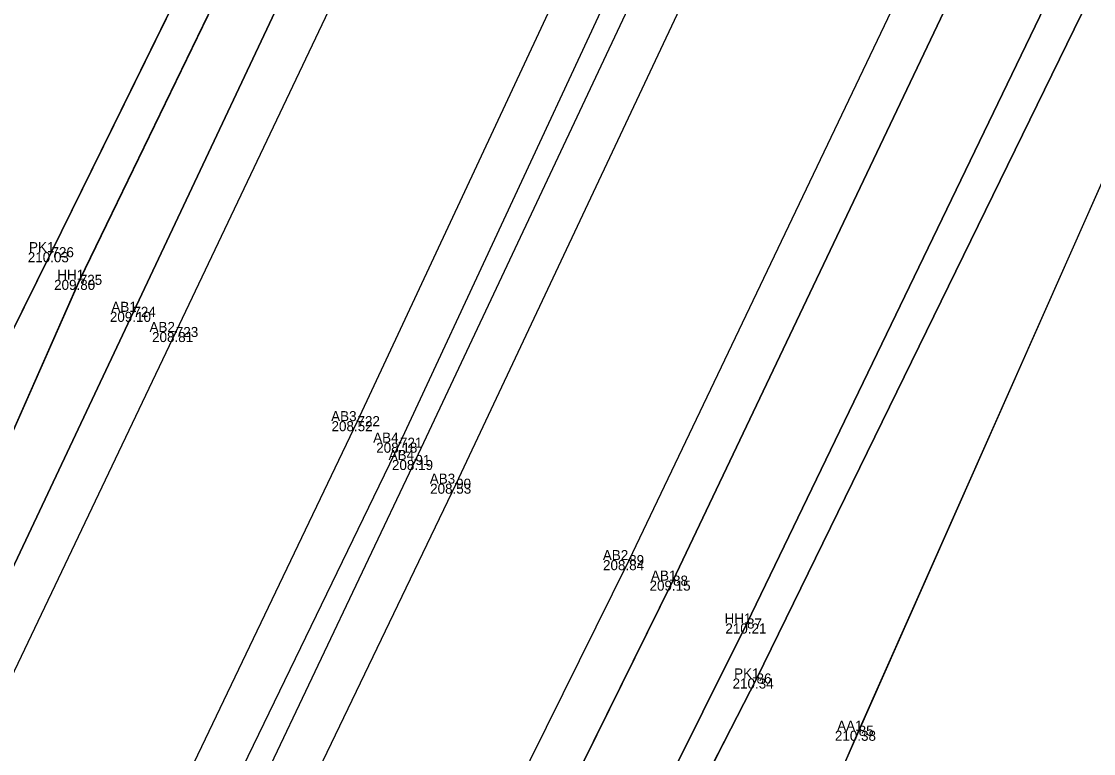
# Model space of a CAD drawing. Extents: x -263091 to -262565, y -1238731 to -1237092.
# Drawn here: x -262786.65 to -262765.31, y -1237663.76 to -1237649.19 of the extents above; entities that cross this region are included whole.
import ezdxf

# ---------------------------------------------------------------- set-up
doc = ezdxf.new("R2010")
doc.units = 0
for name, color, linetype in [('01_Hrana_betónu', 7, 'Continuous'), ('02_Oplotenie', 7, 'Continuous'), ('03_Asfalt', 7, 'Continuous'), ('05_Hrana_terénu', 7, 'Continuous'), ('Groma (21)', 7, 'Continuous'), ('Groma (22)', 7, 'Continuous'), ('Groma (23)', 7, 'Continuous'), ('Groma (24)', 7, 'Continuous'), ('U005_Betónové_panely', 7, 'Continuous'), ('U005_Zeleň_mimo', 7, 'Continuous'), ('U005_Zeleň_vnútro', 7, 'Continuous'), ('U005_Zeleň_zatrávňovač', 7, 'Continuous')]:
    doc.layers.add(name, color=color, linetype=linetype)

msp = doc.modelspace()

# ---------------------------------------------------------------- linework, layer by layer
at = {"layer": '01_Hrana_betónu'}
for points in [[(-262786.432, -1237675.911), (-262784.052, -1237670.991), (-262777.997, -1237658.39), (-262770.22, -1237641.884), (-262760.517, -1237621.621), (-262751.199, -1237602.266), (-262746.917, -1237592.345), (-262743.67, -1237583.59), (-262741.234, -1237574.416), (-262739.924, -1237566.213), (-262738.929, -1237556.596), (-262738.741, -1237547.665), (-262738.506, -1237524.618), (-262738.316, -1237501.393), (-262738.103, -1237478.98), (-262737.841, -1237459.175), (-262737.82, -1237425.07), (-262737.772, -1237401.714), (-262737.893, -1237377.738), (-262738.012, -1237356.488), (-262737.973, -1237332.295), (-262738.006, -1237318.022), (-262737.947, -1237310.645)], [(-262738.855, -1237311.192), (-262738.946, -1237318.051), (-262738.849, -1237332.413), (-262738.867, -1237356.312), (-262738.748, -1237377.69), (-262738.758, -1237401.69), (-262738.753, -1237425.185), (-262738.668, -1237459.096), (-262739.01, -1237478.875), (-262739.257, -1237501.361), (-262739.436, -1237524.506), (-262739.635, -1237547.624), (-262739.863, -1237556.5), (-262740.784, -1237566.075), (-262742.123, -1237574.161), (-262744.555, -1237583.315), (-262747.793, -1237592.067), (-262752.033, -1237601.877), (-262761.381, -1237621.164), (-262771.059, -1237641.465), (-262778.806, -1237657.918), (-262784.861, -1237670.667), (-262787.201, -1237675.529)], [(-262739.343, -1237311.485), (-262739.423, -1237318.909), (-262739.337, -1237332.42), (-262739.334, -1237355.849), (-262739.135, -1237377.701), (-262739.178, -1237401.786), (-262739.257, -1237424.031), (-262739.458, -1237458.924), (-262739.421, -1237479.296), (-262739.718, -1237500.116), (-262739.917, -1237524.824), (-262740.163, -1237546.913), (-262740.342, -1237556.649), (-262741.144, -1237564.78), (-262742.646, -1237573.838), (-262744.715, -1237582.455), (-262748.007, -1237591.229), (-262752.529, -1237601.669), (-262761.584, -1237620.386), (-262771.44, -1237641.076), (-262779.114, -1237657.574), (-262785.318, -1237670.364), (-262787.643, -1237675.31)], [(-262788.441, -1237674.914), (-262786.102, -1237669.974), (-262779.96, -1237657.146), (-262772.255, -1237640.671), (-262762.405, -1237620.082), (-262753.353, -1237601.237), (-262748.855, -1237590.92), (-262745.54, -1237582.117), (-262743.431, -1237573.688), (-262742.016, -1237564.7), (-262741.168, -1237556.501), (-262740.979, -1237546.892), (-262740.851, -1237524.752), (-262740.671, -1237500.08), (-262740.394, -1237479.483), (-262740.216, -1237458.955), (-262740.117, -1237423.647), (-262740.094, -1237401.75), (-262740.13, -1237377.708), (-262740.243, -1237355.929), (-262740.317, -1237332.345), (-262740.44, -1237318.894), (-262740.323, -1237312.076)], [(-262744.671, -1237314.693), (-262744.322, -1237332.28), (-262744.032, -1237356.103), (-262743.621, -1237377.876), (-262743.427, -1237401.834), (-262743.334, -1237423.507), (-262743.665, -1237455.163), (-262743.89, -1237458.66), (-262743.816, -1237479.543), (-262744.125, -1237500.374), (-262744.256, -1237524.891), (-262744.407, -1237545.149), (-262744.747, -1237556.085), (-262745.544, -1237564.593), (-262746.648, -1237572.023), (-262748.879, -1237581.03), (-262752.099, -1237589.665), (-262756.673, -1237599.828), (-262765.314, -1237617.226), (-262775.804, -1237639.013), (-262783.576, -1237655.372), (-262792.033, -1237673.09)], [(-262792.676, -1237672.47), (-262784.421, -1237654.971), (-262776.677, -1237638.569), (-262766.087, -1237616.912), (-262757.487, -1237599.378), (-262752.942, -1237589.379), (-262749.712, -1237580.796), (-262747.504, -1237571.715), (-262746.486, -1237564.414), (-262745.673, -1237555.98), (-262745.336, -1237545.322), (-262745.216, -1237524.737), (-262745.016, -1237500.506), (-262744.745, -1237479.418), (-262744.873, -1237458.479), (-262744.515, -1237455.206), (-262744.284, -1237423.517), (-262744.408, -1237401.828), (-262744.521, -1237377.717), (-262744.916, -1237356.111), (-262745.155, -1237332.402), (-262745.296, -1237327.881), (-262745.213, -1237324.651), (-262745.472, -1237315.175)], [(-262783.258, -1237677.486), (-262783.111, -1237677.185), (-262780.8, -1237672.534), (-262774.552, -1237659.911), (-262766.786, -1237643.656), (-262757.035, -1237623.248), (-262747.974, -1237603.808), (-262743.592, -1237593.531), (-262740.333, -1237584.524), (-262737.7, -1237574.963), (-262736.283, -1237566.732), (-262735.575, -1237556.629), (-262735.369, -1237547.722), (-262734.981, -1237524.159), (-262734.838, -1237501.704)], [(-262782.326, -1237677.959), (-262781.45, -1237675.8), (-262779.987, -1237673.099), (-262773.679, -1237660.319), (-262765.958, -1237644.106), (-262756.238, -1237623.625), (-262747.207, -1237604.197), (-262742.811, -1237593.79), (-262739.484, -1237584.835), (-262736.846, -1237575.127), (-262735.426, -1237566.88), (-262734.686, -1237556.753), (-262734.467, -1237547.755), (-262734.294, -1237524.216), (-262733.894, -1237501.859)]]:
    msp.add_lwpolyline(points, dxfattribs=at)
at = {"layer": '02_Oplotenie'}
for points in [[(-262728.456, -1237307.793), (-262728.519, -1237318.579), (-262728.768, -1237332.338), (-262729.377, -1237356.238), (-262730.032, -1237378.843), (-262730.564, -1237401.661), (-262730.923, -1237425.563), (-262730.973, -1237458.163), (-262731.252, -1237478.578), (-262731.235, -1237502.529), (-262731.31, -1237524.311), (-262731.953, -1237547.895), (-262732.188, -1237556.779), (-262732.808, -1237567.174), (-262734.162, -1237576.139), (-262736.979, -1237586.017), (-262740.293, -1237594.798), (-262745.086, -1237605.537), (-262753.698, -1237624.773), (-262762.903, -1237643.627), (-262772.016, -1237662.266), (-262776.478, -1237670.97)], [(-262793.971, -1237669.784), (-262786.051, -1237653.784), (-262778.339, -1237638.096), (-262767.839, -1237615.998), (-262759.49, -1237598.413), (-262754.828, -1237588.44), (-262751.768, -1237579.927), (-262749.971, -1237571.226), (-262749.021, -1237564.318), (-262748.215, -1237555.413), (-262747.787, -1237545.2), (-262747.818, -1237524.565), (-262747.681, -1237500.551), (-262747.391, -1237479.445), (-262747.231, -1237460.146), (-262746.875, -1237423.458), (-262747.304, -1237401.954), (-262748.156, -1237377.36), (-262748.89, -1237356.224), (-262749.247, -1237329.045)]]:
    msp.add_lwpolyline(points, dxfattribs=at)
at = {"layer": '03_Asfalt'}
msp.add_lwpolyline([(-262724.746, -1237307.401), (-262727.828, -1237308.991), (-262728.093, -1237318.612), (-262728.491, -1237332.383), (-262729.117, -1237356.253), (-262729.803, -1237378.892), (-262730.272, -1237401.612), (-262730.633, -1237425.617), (-262730.625, -1237458.196), (-262731.018, -1237478.61), (-262730.917, -1237502.542), (-262731.001, -1237524.284), (-262731.468, -1237547.904), (-262731.892, -1237556.788), (-262732.535, -1237567.203), (-262733.679, -1237576.214), (-262736.504, -1237586.306), (-262740.104, -1237594.868), (-262744.783, -1237605.686), (-262753.189, -1237625.134), (-262761.527, -1237644.232), (-262769.984, -1237663.306), (-262774.379, -1237673.302), (-262777.928, -1237681.411)], dxfattribs=at)
at = {"layer": '05_Hrana_terénu'}
for points in [[(-262746.684, -1237500.449), (-262746.883, -1237524.672), (-262746.96, -1237545.219), (-262747.259, -1237555.728), (-262748.105, -1237564.398), (-262749.066, -1237571.186), (-262750.795, -1237580.085), (-262754.134, -1237588.771), (-262758.577, -1237598.887), (-262767.121, -1237616.464), (-262785.488, -1237654.334), (-262789.051, -1237662.387), (-262794.016, -1237671.765)], [(-262780.481, -1237679.127), (-262780.184, -1237678.906), (-262778.142, -1237677.63), (-262776.658, -1237673.919), (-262777.447, -1237671.687), (-262772.207, -1237661.172), (-262764.249, -1237644.683), (-262754.484, -1237624.262), (-262745.614, -1237605.143), (-262741.062, -1237594.471), (-262737.644, -1237585.61), (-262735.075, -1237575.555), (-262733.583, -1237567.143), (-262732.968, -1237556.742), (-262732.631, -1237547.918), (-262732.158, -1237524.14), (-262732.188, -1237502.434)]]:
    msp.add_lwpolyline(points, dxfattribs=at)
at = {"layer": 'Groma (21)'}
for centre in [(-262786.051, -1237653.784), (-262785.488, -1237654.334), (-262784.421, -1237654.971), (-262783.576, -1237655.372), (-262779.96, -1237657.146), (-262779.114, -1237657.574), (-262778.806, -1237657.918), (-262777.997, -1237658.39), (-262774.552, -1237659.911), (-262773.679, -1237660.319), (-262772.207, -1237661.172), (-262772.016, -1237662.266), (-262769.984, -1237663.306)]:
    msp.add_circle(centre, 0.01, dxfattribs=at)
at = {"layer": 'U005_Betónové_panely'}
for points in [[(-262783.28, -1237678.88), (-262786.97, -1237677.03), (-262787.74, -1237676.65), (-262788.17, -1237676.43), (-262788.97, -1237676.03), (-262792.52, -1237674.26), (-262791.95, -1237673.18), (-262792.03, -1237673.09), (-262792.68, -1237672.47), (-262784.42, -1237654.97), (-262776.68, -1237638.57), (-262766.09, -1237616.91), (-262757.49, -1237599.38), (-262752.94, -1237589.38), (-262749.71, -1237580.8), (-262747.5, -1237571.72), (-262746.49, -1237564.41), (-262745.67, -1237555.98), (-262745.34, -1237545.32), (-262745.22, -1237524.74), (-262745.02, -1237500.51)], [(-262733.89, -1237501.86), (-262734.29, -1237524.22), (-262734.47, -1237547.76), (-262734.69, -1237556.75), (-262735.43, -1237566.88), (-262736.85, -1237575.13), (-262739.48, -1237584.84), (-262742.81, -1237593.79), (-262747.21, -1237604.2), (-262756.24, -1237623.63), (-262765.96, -1237644.11), (-262773.68, -1237660.32), (-262779.99, -1237673.1), (-262781.45, -1237675.8), (-262782.33, -1237677.96), (-262782.75, -1237677.74), (-262783.28, -1237678.88)], [(-262747.21, -1237604.2), (-262756.24, -1237623.63), (-262765.96, -1237644.11), (-262773.68, -1237660.32), (-262779.99, -1237673.1), (-262781.45, -1237675.8), (-262782.33, -1237677.96), (-262782.75, -1237677.74), (-262783.28, -1237678.88), (-262786.97, -1237677.03), (-262787.74, -1237676.65), (-262788.17, -1237676.43), (-262788.97, -1237676.03), (-262792.52, -1237674.26), (-262791.95, -1237673.18), (-262792.03, -1237673.09), (-262792.68, -1237672.47), (-262784.42, -1237654.97), (-262776.68, -1237638.57), (-262766.09, -1237616.91)]]:
    msp.add_lwpolyline(points, dxfattribs=at)
at = {"layer": 'U005_Zeleň_mimo'}
for points in [[(-262747.68, -1237500.55), (-262747.82, -1237524.57), (-262747.79, -1237545.2), (-262748.22, -1237555.41), (-262749.02, -1237564.32), (-262749.97, -1237571.23), (-262751.77, -1237579.93), (-262754.83, -1237588.44), (-262759.49, -1237598.41), (-262767.84, -1237616), (-262778.34, -1237638.1), (-262786.05, -1237653.78), (-262793.97, -1237669.78), (-262795.54, -1237672.75), (-262808.34, -1237666.36), (-262793.39, -1237627.04), (-262791.78, -1237622.95), (-262787.11, -1237623.75), (-262784.13, -1237624.4), (-262781.33, -1237608.15), (-262778.14, -1237587.84), (-262773.94, -1237562.14), (-262768.34, -1237527.64), (-262757.02, -1237455.96)], [(-262744.78, -1237605.69), (-262753.19, -1237625.13), (-262761.53, -1237644.23), (-262769.98, -1237663.31), (-262774.38, -1237673.3), (-262777.93, -1237681.41), (-262780.92, -1237680.05), (-262780.48, -1237679.13), (-262780.18, -1237678.91), (-262778.14, -1237677.63), (-262776.66, -1237673.92), (-262776.48, -1237670.97), (-262772.02, -1237662.27), (-262762.9, -1237643.63), (-262753.7, -1237624.77), (-262745.09, -1237605.54)]]:
    msp.add_lwpolyline(points, dxfattribs=at)
at = {"layer": 'U005_Zeleň_vnútro'}
for points in [[(-262794.83, -1237673.1), (-262795.54, -1237672.75), (-262793.97, -1237669.78), (-262786.05, -1237653.78), (-262778.34, -1237638.1), (-262767.84, -1237616), (-262759.49, -1237598.41), (-262754.83, -1237588.44), (-262751.77, -1237579.93), (-262749.97, -1237571.23), (-262749.02, -1237564.32), (-262748.22, -1237555.41), (-262747.79, -1237545.2), (-262747.82, -1237524.57), (-262747.68, -1237500.55)], [(-262746.68, -1237500.45), (-262746.88, -1237524.67), (-262746.96, -1237545.22), (-262747.26, -1237555.73), (-262748.11, -1237564.4), (-262749.07, -1237571.19), (-262750.8, -1237580.09), (-262754.13, -1237588.77), (-262758.58, -1237598.89), (-262767.12, -1237616.46), (-262785.49, -1237654.33), (-262789.05, -1237662.39), (-262794.02, -1237671.77), (-262794.42, -1237672.24), (-262794.83, -1237673.1)], [(-262780.48, -1237679.13), (-262780.7, -1237678.43), (-262778.79, -1237677.1), (-262777.54, -1237674.56), (-262778.2, -1237673.69), (-262777.45, -1237671.69), (-262772.21, -1237661.17), (-262764.25, -1237644.68), (-262754.48, -1237624.26), (-262745.61, -1237605.14), (-262741.06, -1237594.47), (-262737.64, -1237585.61), (-262735.08, -1237575.56), (-262733.58, -1237567.14), (-262732.97, -1237556.74), (-262732.63, -1237547.92), (-262732.16, -1237524.14), (-262732.19, -1237502.43)], [(-262731.24, -1237502.53), (-262731.31, -1237524.31), (-262731.95, -1237547.9), (-262732.19, -1237556.78), (-262732.81, -1237567.17), (-262734.16, -1237576.14), (-262736.98, -1237586.02), (-262740.29, -1237594.8), (-262745.09, -1237605.54), (-262753.7, -1237624.77), (-262762.9, -1237643.63), (-262772.02, -1237662.27), (-262776.48, -1237670.97), (-262776.66, -1237673.92), (-262778.14, -1237677.63), (-262780.18, -1237678.91), (-262780.48, -1237679.13)], [(-262745.09, -1237605.54), (-262753.7, -1237624.77), (-262762.9, -1237643.63), (-262772.02, -1237662.27), (-262776.48, -1237670.97), (-262776.66, -1237673.92), (-262778.14, -1237677.63), (-262780.18, -1237678.91), (-262780.48, -1237679.13), (-262780.7, -1237678.43), (-262778.79, -1237677.1), (-262777.54, -1237674.56), (-262778.2, -1237673.69), (-262777.45, -1237671.69), (-262772.21, -1237661.17), (-262764.25, -1237644.68), (-262754.48, -1237624.26), (-262745.61, -1237605.14)], [(-262767.12, -1237616.46), (-262785.49, -1237654.33), (-262789.05, -1237662.39), (-262794.02, -1237671.77), (-262794.42, -1237672.24), (-262794.83, -1237673.1), (-262795.54, -1237672.75), (-262793.97, -1237669.78), (-262786.05, -1237653.78), (-262778.34, -1237638.1), (-262767.84, -1237616)]]:
    msp.add_lwpolyline(points, dxfattribs=at)
at = {"layer": 'U005_Zeleň_zatrávňovač'}
for points in [[(-262792.68, -1237672.47), (-262792.92, -1237672.24), (-262794.02, -1237671.77), (-262789.05, -1237662.39), (-262785.49, -1237654.33), (-262767.12, -1237616.46), (-262758.58, -1237598.89), (-262754.13, -1237588.77), (-262750.8, -1237580.09), (-262749.07, -1237571.19), (-262748.11, -1237564.4), (-262747.26, -1237555.73), (-262746.96, -1237545.22), (-262746.88, -1237524.67), (-262746.68, -1237500.45)], [(-262745.02, -1237500.51), (-262745.22, -1237524.74), (-262745.34, -1237545.32), (-262745.67, -1237555.98), (-262746.49, -1237564.41), (-262747.5, -1237571.72), (-262749.71, -1237580.8), (-262752.94, -1237589.38), (-262757.49, -1237599.38), (-262766.09, -1237616.91), (-262776.68, -1237638.57), (-262784.42, -1237654.97), (-262792.68, -1237672.47)], [(-262778.2, -1237673.69), (-262779.99, -1237673.1), (-262773.68, -1237660.32), (-262765.96, -1237644.11), (-262756.24, -1237623.63), (-262747.21, -1237604.2), (-262742.81, -1237593.79), (-262739.48, -1237584.84), (-262736.85, -1237575.13), (-262735.43, -1237566.88), (-262734.69, -1237556.75), (-262734.47, -1237547.76), (-262734.29, -1237524.22), (-262733.89, -1237501.86)], [(-262732.19, -1237502.43), (-262732.16, -1237524.14), (-262732.63, -1237547.92), (-262732.97, -1237556.74), (-262733.58, -1237567.14), (-262735.08, -1237575.56), (-262737.64, -1237585.61), (-262741.06, -1237594.47), (-262745.61, -1237605.14), (-262754.48, -1237624.26), (-262764.25, -1237644.68), (-262772.21, -1237661.17), (-262777.45, -1237671.69), (-262778.2, -1237673.69)], [(-262745.61, -1237605.14), (-262754.48, -1237624.26), (-262764.25, -1237644.68), (-262772.21, -1237661.17), (-262777.45, -1237671.69), (-262778.2, -1237673.69), (-262779.99, -1237673.1), (-262773.68, -1237660.32), (-262765.96, -1237644.11), (-262756.24, -1237623.63), (-262747.21, -1237604.2)], [(-262766.09, -1237616.91), (-262776.68, -1237638.57), (-262784.42, -1237654.97), (-262792.68, -1237672.47), (-262792.92, -1237672.24), (-262794.02, -1237671.77), (-262789.05, -1237662.39), (-262785.49, -1237654.33), (-262767.12, -1237616.46)]]:
    msp.add_lwpolyline(points, dxfattribs=at)

# ---------------------------------------------------------------- texts
at = {"layer": 'Groma (22)'}
for s, p in [('726', (-262786.051, -1237653.884)), ('725', (-262785.488, -1237654.434)), ('724', (-262784.421, -1237655.071)), ('723', (-262783.576, -1237655.472)), ('722', (-262779.96, -1237657.246)), ('721', (-262779.114, -1237657.674)), ('91', (-262778.806, -1237658.018)), ('90', (-262777.997, -1237658.49)), ('89', (-262774.552, -1237660.011)), ('88', (-262773.679, -1237660.419)), ('87', (-262772.207, -1237661.272)), ('86', (-262772.016, -1237662.366)), ('85', (-262769.984, -1237663.406))]:
    msp.add_text(s, height=0.2, dxfattribs=at).set_placement(p)
at = {"layer": 'Groma (23)'}
for s, p in [('210.03', (-262786.523, -1237653.984)), ('209.80', (-262785.999, -1237654.534)), ('209.10', (-262784.889, -1237655.171)), ('208.81', (-262784.049, -1237655.572)), ('208.52', (-262780.477, -1237657.346)), ('208.18', (-262779.587, -1237657.774)), ('208.19', (-262779.274, -1237658.118)), ('208.53', (-262778.514, -1237658.59)), ('208.84', (-262775.073, -1237660.111)), ('209.15', (-262774.147, -1237660.519)), ('210.21', (-262772.637, -1237661.372)), ('210.34', (-262772.494, -1237662.466)), ('210.38', (-262770.457, -1237663.506))]:
    msp.add_text(s, height=0.2, dxfattribs=at).set_placement(p)
at = {"layer": 'Groma (24)'}
for s, p in [('PK1', (-262786.498, -1237653.784)), ('HH1', (-262785.935, -1237654.334)), ('AB1', (-262784.859, -1237654.971)), ('AB2', (-262784.1, -1237655.372)), ('AB3', (-262780.484, -1237657.146)), ('AB4', (-262779.648, -1237657.574)), ('AB4', (-262779.34, -1237657.918)), ('AB3', (-262778.521, -1237658.39)), ('AB2', (-262775.076, -1237659.911)), ('AB1', (-262774.117, -1237660.319)), ('HH1', (-262772.654, -1237661.172)), ('PK1', (-262772.463, -1237662.266)), ('AA1', (-262770.412, -1237663.306))]:
    msp.add_text(s, height=0.2, dxfattribs=at).set_placement(p)

doc.saveas('drawing.dxf')
